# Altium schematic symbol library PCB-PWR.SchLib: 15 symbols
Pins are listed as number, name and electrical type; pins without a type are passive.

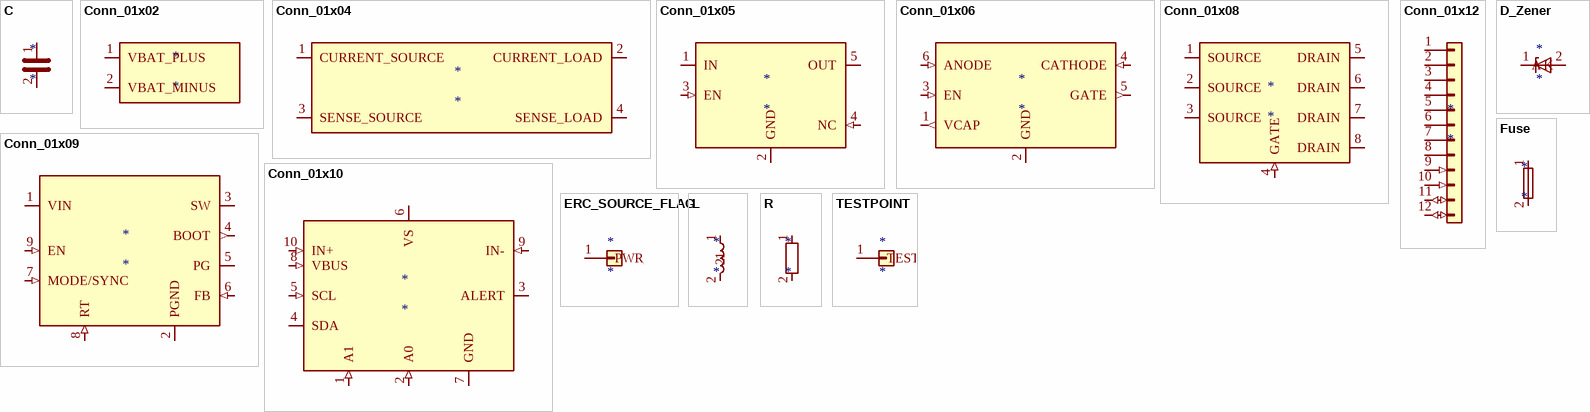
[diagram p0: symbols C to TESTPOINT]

## C
designator *
pins: 1, 2

## Conn_01x02
designator *
pins: 1 VBAT_PLUS, 2 VBAT_MINUS

## Conn_01x04
designator *
pins: 1 CURRENT_SOURCE, 2 CURRENT_LOAD, 3 SENSE_SOURCE, 4 SENSE_LOAD

## Conn_01x05
designator *
pins: 1 IN (power), 2 GND (power), 3 EN (in), 4 NC (in), 5 OUT (power)

## Conn_01x06
designator *
pins: 1 VCAP (out), 2 GND (power), 3 EN (in), 4 CATHODE (in), 5 GATE (out), 6 ANODE (in)

## Conn_01x08
designator *
pins: 1 SOURCE, 2 SOURCE, 3 SOURCE, 4 GATE (in), 5 DRAIN, 6 DRAIN, 7 DRAIN, 8 DRAIN

## Conn_01x09
designator *
pins: 1 VIN (power), 2 PGND (power), 3 SW (power), 4 BOOT (out), 5 PG (oc), 6 FB (in), 7 MODE/SYNC (in), 8 RT (in), 9 EN (in)

## Conn_01x10
designator *
pins: 1 A1 (in), 2 A0 (in), 3 ALERT (oc), 4 SDA (io), 5 SCL (in), 6 VS (power), 7 GND (power), 8 VBUS (in), 9 IN- (in), 10 IN+ (in)

## Conn_01x12
designator *
pins: 1 3V8_MODEM, 2 GND_MODEM, 3 3V3_DIGITAL, 4 GND_DIGITAL, 5 1V8_MIC, 6 GND_MIC, 7 PWR_GOOD (oc), 8 FAULT (oc), 9 EN_MODEM (in), 10 EN_AUX (in), 11 I2C2_SCL (io), 12 I2C2_SDA (io)

## D_Zener
designator *
pins: 1 K, 2 A

## ERC_SOURCE_FLAG
designator *
pins: 1 PWR_SOURCE (power)

## Fuse
designator *
pins: 1, 2

## L
designator *
pins: 1, 2

## R
designator *
pins: 1, 2

## TESTPOINT
designator *
pins: 1 TEST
